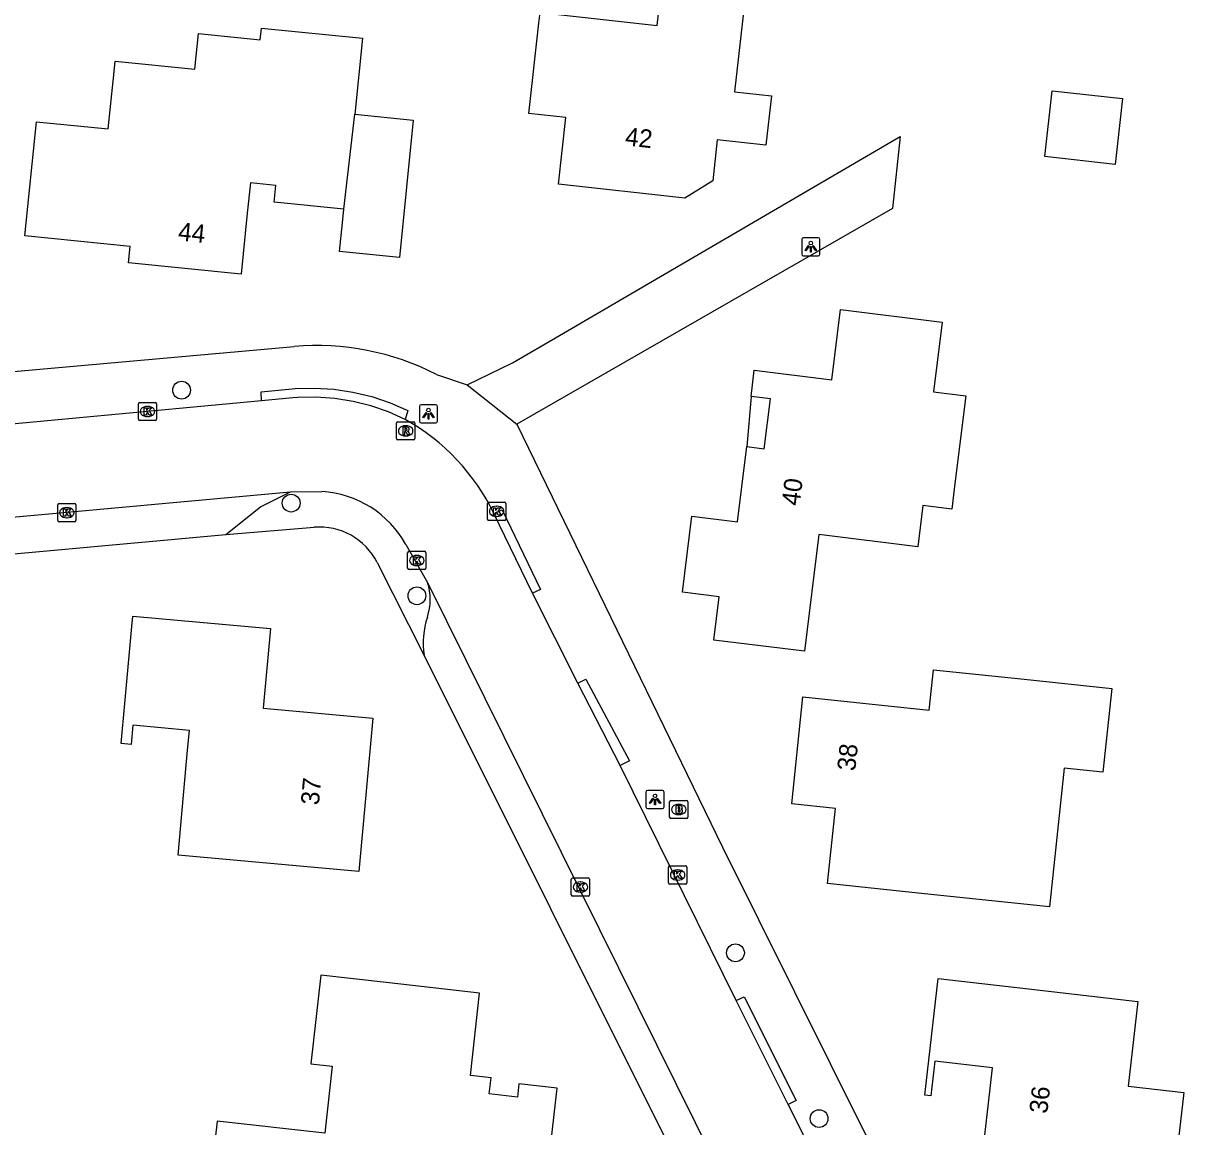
# Model space of a CAD drawing. Extents: x 162398 to 163643, y 386453 to 387397.
# Drawn here: x 163120.8 to 163184.6, y 386684.2 to 386744.8 of the extents above; entities that cross this region are included whole.
import ezdxf

# ---------------------------------------------------------------- set-up
doc = ezdxf.new("R2010")
doc.units = 0
for name, color, linetype in [('IMGEO_Boom', 7, 'Continuous'), ('IMGEO_Brandkraan', 7, 'Continuous'), ('IMGEO_Kolk', 7, 'Continuous'), ('IMGEO_Lichtpunt', 7, 'Continuous'), ('IMGEO_Pand', 7, 'Continuous'), ('IMGEO_Pand_nummerreeks', 7, 'Continuous'), ('IMGEO_Pand_overbouw', 7, 'Continuous'), ('IMGEO_Parkeervlak_open', 7, 'Continuous'), ('IMGEO_Rijbaan_lokaal_open', 7, 'Continuous'), ('IMGEO_Rioolput', 7, 'Continuous'), ('IMGEO_Voetpad_open', 7, 'Continuous')]:
    doc.layers.add(name, color=color, linetype=linetype)

msp = doc.modelspace()

# ---------------------------------------------------------------- linework, layer by layer
at = {"layer": 'IMGEO_Boom'}
for centre in [(163129.517, 386724.678), (163135.538, 386718.476), (163142.45, 386713.386), (163159.955, 386693.777), (163164.55, 386684.674)]:
    msp.add_circle(centre, 0.489, dxfattribs=at)
at = {"layer": 'IMGEO_Brandkraan'}
for p, q in [((163156.337, 386701.223), (163156.337, 386702.075)), ((163156.412, 386702.149), (163157.264, 386702.149)), ((163156.825, 386701.929), (163156.85, 386701.929)), ((163157.338, 386702.075), (163157.338, 386701.223)), ((163156.848, 386701.369), (163156.823, 386701.369)), ((163157.264, 386701.149), (163156.412, 386701.149))]:
    msp.add_line(p, q, dxfattribs=at)
for points in [[(163156.337, 386701.223), (163156.337, 386702.075)], [(163156.412, 386702.149), (163157.264, 386702.149)], [(163156.685, 386701.849), (163156.685, 386701.449), (163156.898, 386701.449)], [(163156.916, 386701.849), (163156.685, 386701.849)], [(163157.338, 386702.075), (163157.338, 386701.223)], [(163156.864, 386701.768), (163156.81, 386701.768), (163156.81, 386701.692)], [(163156.81, 386701.692), (163156.863, 386701.692)], [(163156.872, 386701.616), (163156.81, 386701.616), (163156.81, 386701.535)], [(163156.81, 386701.535), (163156.872, 386701.535)], [(163157.264, 386701.149), (163156.412, 386701.149)]]:
    msp.add_lwpolyline(points, dxfattribs=at)
for centre, radius, start, end in [((163156.414, 386702.073), 0.0765, 91.55205, 178.44795), ((163156.414, 386702.073), 0.0765, 91.55205, 178.44795), ((163156.92, 386701.704), 0.145, 59.4692, 91.53667), ((163156.945, 386701.751), 0.0922, 285.51372, 58.15012), ((163157.262, 386702.073), 0.0765, 1.55205, 88.44795), ((163157.262, 386702.073), 0.0765, 1.55205, 88.44795), ((163156.414, 386701.225), 0.0765, 181.55205, 268.44795), ((163156.414, 386701.225), 0.0765, 181.55205, 268.44795), ((163156.865, 386701.73), 0.0379, 267.82845, 90.93552), ((163156.873, 386701.575), 0.0404, 269.87594, 90.50774), ((163156.904, 386701.7), 0.251, 268.66757, 293.53466), ((163156.95, 386701.559), 0.105, 301.31148, 78.98903), ((163157.262, 386701.225), 0.0765, 271.55205, 358.44795), ((163157.262, 386701.225), 0.0765, 271.55205, 358.44795)]:
    msp.add_arc(centre, radius, start, end, dxfattribs=at)
for centre, major_axis, ratio, start_param, end_param in [((163156.824, 386701.649), (-0.387, 0.002), 0.722429, 4.712389, 7.853982), ((163156.849, 386701.649), (-0.39, 0.002), 0.717154, 1.570796, 4.712389)]:
    msp.add_ellipse(centre, major_axis=major_axis, ratio=ratio, start_param=start_param, end_param=end_param, dxfattribs=at)
at = {"layer": 'IMGEO_Kolk'}
for p, q in [((163127.141, 386723.082), (163127.141, 386723.934)), ((163127.216, 386724.008), (163128.068, 386724.008)), ((163127.629, 386723.788), (163127.654, 386723.788)), ((163128.142, 386723.934), (163128.142, 386723.082)), ((163128.068, 386723.008), (163127.216, 386723.008)), ((163127.652, 386723.228), (163127.627, 386723.228)), ((163122.783, 386718.453), (163123.635, 386718.453)), ((163146.33, 386717.596), (163146.33, 386718.448)), ((163146.405, 386718.522), (163147.257, 386718.522)), ((163147.331, 386718.448), (163147.331, 386717.596)), ((163122.708, 386717.527), (163122.708, 386718.379)), ((163123.196, 386718.233), (163123.221, 386718.233)), ((163123.709, 386718.379), (163123.709, 386717.527)), ((163146.818, 386718.302), (163146.843, 386718.302)), ((163123.635, 386717.453), (163122.783, 386717.453)), ((163123.219, 386717.673), (163123.194, 386717.673)), ((163147.257, 386717.522), (163146.405, 386717.522)), ((163146.841, 386717.742), (163146.816, 386717.742)), ((163141.939, 386714.902), (163141.939, 386715.754)), ((163142.014, 386715.828), (163142.866, 386715.828)), ((163142.427, 386715.608), (163142.452, 386715.608)), ((163142.94, 386715.754), (163142.94, 386714.902)), ((163142.866, 386714.828), (163142.014, 386714.828)), ((163142.45, 386715.048), (163142.425, 386715.048)), ((163156.278, 386697.627), (163156.278, 386698.479)), ((163156.353, 386698.553), (163157.205, 386698.553)), ((163156.766, 386698.333), (163156.791, 386698.333)), ((163157.279, 386698.479), (163157.279, 386697.627)), ((163150.933, 386696.962), (163150.933, 386697.814)), ((163151.008, 386697.888), (163151.86, 386697.888)), ((163151.421, 386697.668), (163151.446, 386697.668)), ((163151.934, 386697.814), (163151.934, 386696.962)), ((163157.205, 386697.553), (163156.353, 386697.553)), ((163156.789, 386697.773), (163156.764, 386697.773)), ((163151.86, 386696.888), (163151.008, 386696.888)), ((163151.444, 386697.108), (163151.419, 386697.108))]:
    msp.add_line(p, q, dxfattribs=at)
for points in [[(163127.141, 386723.082), (163127.141, 386723.934)], [(163127.216, 386724.008), (163128.068, 386724.008)], [(163127.462, 386723.708), (163127.585, 386723.708), (163127.585, 386723.557), (163127.715, 386723.708), (163127.879, 386723.708), (163127.733, 386723.557), (163127.886, 386723.308), (163127.734, 386723.308), (163127.649, 386723.472), (163127.585, 386723.405), (163127.585, 386723.308), (163127.462, 386723.308), (163127.462, 386723.708)], [(163128.142, 386723.934), (163128.142, 386723.082)], [(163128.068, 386723.008), (163127.216, 386723.008)], [(163122.783, 386718.453), (163123.635, 386718.453)], [(163146.33, 386717.596), (163146.33, 386718.448)], [(163146.405, 386718.522), (163147.257, 386718.522)], [(163147.331, 386718.448), (163147.331, 386717.596)], [(163122.708, 386717.527), (163122.708, 386718.379)], [(163123.029, 386718.153), (163123.152, 386718.153), (163123.152, 386718.002), (163123.282, 386718.153), (163123.446, 386718.153), (163123.3, 386718.002), (163123.453, 386717.753), (163123.301, 386717.753), (163123.216, 386717.917), (163123.152, 386717.85), (163123.152, 386717.753), (163123.029, 386717.753), (163123.029, 386718.153)], [(163123.709, 386718.379), (163123.709, 386717.527)], [(163146.651, 386718.222), (163146.774, 386718.222), (163146.774, 386718.071), (163146.904, 386718.222), (163147.068, 386718.222), (163146.922, 386718.071), (163147.075, 386717.822), (163146.923, 386717.822), (163146.838, 386717.986), (163146.774, 386717.919), (163146.774, 386717.822), (163146.651, 386717.822), (163146.651, 386718.222)], [(163123.635, 386717.453), (163122.783, 386717.453)], [(163147.257, 386717.522), (163146.405, 386717.522)], [(163141.939, 386714.902), (163141.939, 386715.754)], [(163142.014, 386715.828), (163142.866, 386715.828)], [(163142.26, 386715.528), (163142.383, 386715.528), (163142.383, 386715.377), (163142.513, 386715.528), (163142.677, 386715.528), (163142.531, 386715.377), (163142.684, 386715.128), (163142.532, 386715.128), (163142.447, 386715.292), (163142.383, 386715.225), (163142.383, 386715.128), (163142.26, 386715.128), (163142.26, 386715.528)], [(163142.94, 386715.754), (163142.94, 386714.902)], [(163142.866, 386714.828), (163142.014, 386714.828)], [(163156.278, 386697.627), (163156.278, 386698.479)], [(163156.353, 386698.553), (163157.205, 386698.553)], [(163156.599, 386698.253), (163156.722, 386698.253), (163156.722, 386698.102), (163156.852, 386698.253), (163157.016, 386698.253), (163156.87, 386698.102), (163157.023, 386697.853), (163156.871, 386697.853), (163156.786, 386698.017), (163156.722, 386697.95), (163156.722, 386697.853), (163156.599, 386697.853), (163156.599, 386698.253)], [(163157.279, 386698.479), (163157.279, 386697.627)], [(163150.933, 386696.962), (163150.933, 386697.814)], [(163151.008, 386697.888), (163151.86, 386697.888)], [(163151.254, 386697.588), (163151.377, 386697.588), (163151.377, 386697.437), (163151.507, 386697.588), (163151.671, 386697.588), (163151.525, 386697.437), (163151.678, 386697.188), (163151.526, 386697.188), (163151.441, 386697.352), (163151.377, 386697.285), (163151.377, 386697.188), (163151.254, 386697.188), (163151.254, 386697.588)], [(163151.934, 386697.814), (163151.934, 386696.962)], [(163157.205, 386697.553), (163156.353, 386697.553)], [(163151.86, 386696.888), (163151.008, 386696.888)]]:
    msp.add_lwpolyline(points, dxfattribs=at)
for centre, start, end in [((163127.218, 386723.932), 91.55205, 178.44795), ((163127.218, 386723.932), 91.55205, 178.44795), ((163128.066, 386723.932), 1.55205, 88.44795), ((163128.066, 386723.932), 1.55205, 88.44795), ((163127.218, 386723.084), 181.55205, 268.44795), ((163127.218, 386723.084), 181.55205, 268.44795), ((163128.066, 386723.084), 271.55205, 358.44795), ((163128.066, 386723.084), 271.55205, 358.44795), ((163122.785, 386718.377), 91.55205, 178.44795), ((163122.785, 386718.377), 91.55205, 178.44795), ((163123.633, 386718.377), 1.55205, 88.44795), ((163123.633, 386718.377), 1.55205, 88.44795), ((163146.407, 386718.446), 91.55205, 178.44795), ((163146.407, 386718.446), 91.55205, 178.44795), ((163147.255, 386718.446), 1.55205, 88.44795), ((163147.255, 386718.446), 1.55205, 88.44795), ((163122.785, 386717.529), 181.55205, 268.44795), ((163122.785, 386717.529), 181.55205, 268.44795), ((163123.633, 386717.529), 271.55205, 358.44795), ((163123.633, 386717.529), 271.55205, 358.44795), ((163146.407, 386717.598), 181.55205, 268.44795), ((163146.407, 386717.598), 181.55205, 268.44795), ((163147.255, 386717.598), 271.55205, 358.44795), ((163147.255, 386717.598), 271.55205, 358.44795), ((163142.016, 386715.752), 91.55205, 178.44795), ((163142.016, 386715.752), 91.55205, 178.44795), ((163142.864, 386715.752), 1.55205, 88.44795), ((163142.864, 386715.752), 1.55205, 88.44795), ((163142.016, 386714.904), 181.55205, 268.44795), ((163142.016, 386714.904), 181.55205, 268.44795), ((163142.864, 386714.904), 271.55205, 358.44795), ((163142.864, 386714.904), 271.55205, 358.44795), ((163156.355, 386698.477), 91.55205, 178.44795), ((163156.355, 386698.477), 91.55205, 178.44795), ((163157.203, 386698.477), 1.55205, 88.44795), ((163157.203, 386698.477), 1.55205, 88.44795), ((163151.01, 386697.812), 91.55205, 178.44795), ((163151.01, 386697.812), 91.55205, 178.44795), ((163151.858, 386697.812), 1.55205, 88.44795), ((163151.858, 386697.812), 1.55205, 88.44795), ((163156.355, 386697.629), 181.55205, 268.44795), ((163156.355, 386697.629), 181.55205, 268.44795), ((163157.203, 386697.629), 271.55205, 358.44795), ((163157.203, 386697.629), 271.55205, 358.44795), ((163151.01, 386696.964), 181.55205, 268.44795), ((163151.01, 386696.964), 181.55205, 268.44795), ((163151.858, 386696.964), 271.55205, 358.44795), ((163151.858, 386696.964), 271.55205, 358.44795)]:
    msp.add_arc(centre, 0.0765, start, end, dxfattribs=at)
for centre, major_axis, ratio, start_param, end_param in [((163127.628, 386723.508), (-0.387, 0.002), 0.722429, 4.712389, 7.853982), ((163127.653, 386723.508), (-0.39, 0.002), 0.717154, 1.570796, 4.712389), ((163123.195, 386717.953), (-0.387, 0.002), 0.722429, 4.712389, 7.853982), ((163123.22, 386717.953), (-0.39, 0.002), 0.717154, 1.570796, 4.712389), ((163146.817, 386718.022), (-0.387, 0.002), 0.722429, 4.712389, 7.853982), ((163146.842, 386718.022), (-0.39, 0.002), 0.717154, 1.570796, 4.712389), ((163142.426, 386715.328), (-0.387, 0.002), 0.722429, 4.712389, 7.853982), ((163142.451, 386715.328), (-0.39, 0.002), 0.717154, 1.570796, 4.712389), ((163156.765, 386698.053), (-0.387, 0.002), 0.722429, 4.712389, 7.853982), ((163156.79, 386698.053), (-0.39, 0.002), 0.717154, 1.570796, 4.712389), ((163151.42, 386697.388), (-0.387, 0.002), 0.722429, 4.712389, 7.853982), ((163151.445, 386697.388), (-0.39, 0.002), 0.717154, 1.570796, 4.712389)]:
    msp.add_ellipse(centre, major_axis=major_axis, ratio=ratio, start_param=start_param, end_param=end_param, dxfattribs=at)
at = {"layer": 'IMGEO_Lichtpunt'}
for p, q in [((163163.598, 386732.957), (163163.598, 386732.15)), ((163163.598, 386732.957), (163163.598, 386732.15)), ((163164.5, 386733.052), (163163.692, 386733.052)), ((163164.5, 386733.052), (163163.692, 386733.052)), ((163164.594, 386732.15), (163164.594, 386732.957)), ((163164.594, 386732.15), (163164.594, 386732.957)), ((163163.692, 386732.056), (163164.5, 386732.056)), ((163163.692, 386732.056), (163164.5, 386732.056)), ((163142.583, 386723.785), (163142.583, 386722.978)), ((163142.583, 386723.785), (163142.583, 386722.978)), ((163143.485, 386723.88), (163142.677, 386723.88)), ((163143.485, 386723.88), (163142.677, 386723.88)), ((163143.579, 386722.978), (163143.579, 386723.785)), ((163143.579, 386722.978), (163143.579, 386723.785)), ((163142.677, 386722.884), (163143.485, 386722.884)), ((163142.677, 386722.884), (163143.485, 386722.884)), ((163155.035, 386702.602), (163155.035, 386701.795)), ((163155.035, 386702.602), (163155.035, 386701.795)), ((163155.937, 386702.697), (163155.129, 386702.697)), ((163155.937, 386702.697), (163155.129, 386702.697)), ((163156.031, 386701.795), (163156.031, 386702.602)), ((163156.031, 386701.795), (163156.031, 386702.602)), ((163155.129, 386701.701), (163155.937, 386701.701)), ((163155.129, 386701.701), (163155.937, 386701.701))]:
    msp.add_line(p, q, dxfattribs=at)
for points in [[(163163.972, 386732.621), (163164.011, 386732.593), (163163.823, 386732.331), (163163.785, 386732.358), (163163.972, 386732.621)], [(163164.074, 386732.573), (163164.121, 386732.573), (163164.121, 386732.251), (163164.074, 386732.251), (163164.074, 386732.573)], [(163164.184, 386732.593), (163164.222, 386732.62), (163164.409, 386732.358), (163164.37, 386732.33), (163164.184, 386732.593)], [(163142.957, 386723.449), (163142.996, 386723.421), (163142.808, 386723.159), (163142.77, 386723.186), (163142.957, 386723.449)], [(163143.059, 386723.401), (163143.106, 386723.401), (163143.106, 386723.079), (163143.059, 386723.079), (163143.059, 386723.401)], [(163143.169, 386723.421), (163143.207, 386723.448), (163143.394, 386723.186), (163143.355, 386723.158), (163143.169, 386723.421)], [(163155.409, 386702.266), (163155.448, 386702.238), (163155.26, 386701.976), (163155.222, 386702.003), (163155.409, 386702.266)], [(163155.511, 386702.218), (163155.558, 386702.218), (163155.558, 386701.896), (163155.511, 386701.896), (163155.511, 386702.218)], [(163155.621, 386702.238), (163155.659, 386702.265), (163155.846, 386702.003), (163155.807, 386701.975), (163155.621, 386702.238)]]:
    msp.add_lwpolyline(points, dxfattribs=at)
for centre in [(163164.097, 386732.755), (163143.082, 386723.583), (163155.534, 386702.4)]:
    msp.add_circle(centre, 0.0994, dxfattribs=at)
for centre, start, end in [((163163.692, 386732.957), 90, 180), ((163163.692, 386732.957), 90, 180), ((163164.5, 386732.957), 0, 90), ((163164.5, 386732.957), 0, 90), ((163163.692, 386732.15), 180, 270), ((163163.692, 386732.15), 180, 270), ((163164.5, 386732.15), 270, 0), ((163164.5, 386732.15), 270, 360), ((163142.677, 386723.785), 90, 180), ((163142.677, 386723.785), 90, 180), ((163143.485, 386723.785), 0, 90), ((163143.485, 386723.785), 0, 90), ((163142.677, 386722.978), 180, 270), ((163142.677, 386722.978), 180, 270), ((163143.485, 386722.978), 270, 0), ((163143.485, 386722.978), 270, 360), ((163155.129, 386702.602), 90, 180), ((163155.129, 386702.602), 90, 180), ((163155.937, 386702.602), 0, 90), ((163155.937, 386702.602), 0, 90), ((163155.129, 386701.795), 180, 270), ((163155.129, 386701.795), 180, 270), ((163155.937, 386701.795), 270, 0), ((163155.937, 386701.795), 270, 360)]:
    msp.add_arc(centre, 0.0946, start, end, dxfattribs=at)
at = {"layer": 'IMGEO_Pand'}
for points in [[(163150.221, 386736.002), (163150.626, 386739.649), (163148.597, 386739.874), (163149.149, 386744.844), (163149.213, 386745.417), (163155.657, 386744.701), (163156.067, 386748.394), (163160.664, 386747.883), (163159.907, 386741.069), (163161.93, 386740.844), (163161.629, 386738.133), (163158.956, 386738.43), (163158.706, 386736.18), (163157.165, 386735.23), (163150.221, 386736.002)], [(163138.433, 386734.62), (163134.601, 386735.006), (163134.693, 386735.922), (163133.294, 386736.063), (163133.126, 386734.394), (163132.789, 386731.051), (163126.6, 386731.675), (163126.69, 386732.57), (163120.909, 386733.152), (163121.54, 386739.421), (163125.484, 386739.024), (163125.783, 386741.991), (163125.86, 386742.753), (163130.25, 386742.311), (163130.447, 386744.262), (163133.836, 386743.92), (163133.901, 386744.565), (163139.455, 386744.006), (163139.035, 386739.832)], [(163176.957, 386737.513), (163177.363, 386741.125), (163181.23, 386740.69), (163180.824, 386737.078), (163176.957, 386737.513)], [(163139.035, 386739.832), (163142.244, 386739.509), (163141.484, 386731.961), (163138.198, 386732.292), (163138.357, 386733.867), (163138.433, 386734.62)], [(163138.433, 386734.62), (163139.035, 386739.832)], [(163164.546, 386716.746), (163163.757, 386710.339), (163158.768, 386710.954), (163159.061, 386713.334), (163157.046, 386713.583), (163157.561, 386717.761), (163160.068, 386717.452), (163160.577, 386721.584), (163161.536, 386721.466), (163161.874, 386724.208), (163160.81, 386724.339), (163160.987, 386725.772), (163165.248, 386725.247), (163165.724, 386729.103), (163171.318, 386728.413), (163170.846, 386724.587), (163172.614, 386724.369), (163172.002, 386719.407), (163171.847, 386718.151), (163170.254, 386718.347), (163169.974, 386716.077), (163164.546, 386716.746)], [(163129.325, 386699.138), (163129.845, 386704.912), (163129.942, 386705.993), (163126.845, 386706.272), (163126.751, 386705.223), (163126.202, 386705.272), (163126.4, 386707.47), (163126.782, 386711.703), (163126.833, 386712.27), (163134.393, 386711.589), (163134, 386707.217), (163140.024, 386706.674), (163139.264, 386698.243), (163129.325, 386699.138)], [(163169.992, 386697.06), (163165.019, 386697.582), (163165.452, 386701.7), (163163.049, 386701.952), (163163.666, 386707.834), (163170.608, 386707.105), (163170.841, 386709.324), (163175.814, 386708.802), (163180.631, 386708.296), (163180.148, 386703.698), (163178.019, 386703.921), (163177.219, 386696.302), (163169.992, 386697.06)], [(163146.421, 386686.029), (163146.521, 386686.908), (163145.387, 386687.036), (163145.897, 386691.563), (163140.929, 386692.124), (163137.171, 386692.548), (163136.622, 386687.682), (163137.795, 386687.55), (163137.381, 386683.873), (163131.471, 386684.538), (163130.905, 386679.525), (163138.51, 386678.666), (163138.658, 386679.979), (163144.328, 386679.34), (163149.296, 386678.779), (163150.149, 386686.343), (163148.058, 386686.579), (163147.976, 386685.854), (163146.421, 386686.029)], [(163181.54, 386686.451), (163184.594, 386686.103), (163183.742, 386678.629), (163183.343, 386678.674), (163183.401, 386679.175), (163177.536, 386679.843), (163177.444, 386679.039), (163176.436, 386679.154), (163176.519, 386679.882), (163173.255, 386680.254), (163173.855, 386685.523), (163174.076, 386687.46), (163170.913, 386687.82), (163170.696, 386685.914), (163170.357, 386685.952), (163171.087, 386692.36), (163176.055, 386691.794), (163182.07, 386691.109), (163181.54, 386686.451)]]:
    msp.add_lwpolyline(points, dxfattribs=at)
at = {"layer": 'IMGEO_Pand_overbouw'}
msp.add_lwpolyline([(163161.874, 386724.208), (163160.81, 386724.339), (163160.577, 386721.584), (163161.536, 386721.466)], close=True, dxfattribs=at)
at = {"layer": 'IMGEO_Parkeervlak_open'}
for points in [[(163106.635, 386714.454), (163131.948, 386716.758)], [(163142.845, 386710.112), (163170.644, 386654.483)]]:
    msp.add_lwpolyline(points, dxfattribs=at)
at = {"layer": 'IMGEO_Rijbaan_lokaal_open'}
for points in [[(163141.811, 386723.064), (163140.884, 386723.484), (163139.923, 386723.819), (163138.936, 386724.066), (163137.931, 386724.225), (163136.916, 386724.293), (163135.898, 386724.271), (163135.635, 386724.25), (163133.912, 386724.09)], [(163133.912, 386724.09), (163118.21, 386722.627)], [(163103.144, 386716.11), (163103.286, 386716.164), (163135.507, 386719.088)], [(163135.507, 386719.088), (163137.228, 386719.108)], [(163148.797, 386713.522), (163146.679, 386717.903)], [(163141.845, 386716.199), (163143.039, 386714.124)], [(163143.039, 386714.124), (163158.79, 386682.361), (163170.35, 386659.122)], [(163151.289, 386708.591), (163148.797, 386713.522)], [(163153.617, 386704.068), (163151.289, 386708.591)], [(163160.001, 386691.151), (163153.617, 386704.068)], [(163162.859, 386685.444), (163160.001, 386691.151)], [(163168.446, 386674.337), (163162.859, 386685.444)]]:
    msp.add_lwpolyline(points, dxfattribs=at)
for centre, radius, start, end in [((163136.112, 386712.812), 11.729, 25.72248, 60.93065), ((163136.889, 386713.452), 5.666, 28.99989, 86.57311)]:
    msp.add_arc(centre, radius, start, end, dxfattribs=at)
at = {"layer": 'IMGEO_Rioolput'}
for p, q in [((163141.331, 386722.02), (163141.331, 386722.872)), ((163141.406, 386722.946), (163142.258, 386722.946)), ((163142.332, 386722.872), (163142.332, 386722.02)), ((163141.819, 386722.726), (163141.844, 386722.726)), ((163142.258, 386721.946), (163141.406, 386721.946)), ((163141.842, 386722.166), (163141.817, 386722.166))]:
    msp.add_line(p, q, dxfattribs=at)
for points in [[(163141.331, 386722.02), (163141.331, 386722.872)], [(163141.406, 386722.946), (163142.258, 386722.946)], [(163142.332, 386722.872), (163142.332, 386722.02)], [(163141.92, 386722.644), (163141.668, 386722.646), (163141.668, 386722.246)], [(163141.668, 386722.246), (163141.792, 386722.246), (163141.792, 386722.408), (163141.803, 386722.408)], [(163141.846, 386722.565), (163141.792, 386722.565), (163141.792, 386722.484)], [(163141.792, 386722.484), (163141.844, 386722.484)], [(163141.85, 386722.379), (163141.921, 386722.246), (163142.061, 386722.246), (163141.996, 386722.372)], [(163142.258, 386721.946), (163141.406, 386721.946)]]:
    msp.add_lwpolyline(points, dxfattribs=at)
for centre, radius, start, end in [((163141.408, 386722.87), 0.0765, 91.55205, 178.44795), ((163141.408, 386722.87), 0.0765, 91.55205, 178.44795), ((163142.256, 386722.87), 0.0765, 1.55205, 88.44795), ((163142.256, 386722.87), 0.0765, 1.55205, 88.44795), ((163141.802, 386722.355), 0.0533, 26.02933, 88.69889), ((163141.828, 386722.673), 0.19, 274.7715, 282.96867), ((163141.852, 386722.469), 0.0964, 77.00612, 93.18647), ((163141.866, 386722.526), 0.0378, 276.66336, 79.67722), ((163141.919, 386722.534), 0.109, 350.36119, 89.41601), ((163141.917, 386722.534), 0.112, 277.58423, 350.98172), ((163141.901, 386722.319), 0.108, 29.51342, 73.79051), ((163141.408, 386722.022), 0.0765, 181.55205, 268.44795), ((163141.408, 386722.022), 0.0765, 181.55205, 268.44795), ((163142.256, 386722.022), 0.0765, 271.55205, 358.44795), ((163142.256, 386722.022), 0.0765, 271.55205, 358.44795)]:
    msp.add_arc(centre, radius, start, end, dxfattribs=at)
for centre, major_axis, ratio, start_param, end_param in [((163141.818, 386722.446), (-0.387, 0.002), 0.722429, 4.712389, 7.853982), ((163141.843, 386722.446), (-0.39, 0.002), 0.717154, 1.570796, 4.712389)]:
    msp.add_ellipse(centre, major_axis=major_axis, ratio=ratio, start_param=start_param, end_param=end_param, dxfattribs=at)
at = {"layer": 'IMGEO_Voetpad_open'}
for points in [[(163145.202, 386724.977), (163147.694, 386726.173), (163150.289, 386727.687), (163169.003, 386738.606), (163168.577, 386734.666), (163147.937, 386722.815)], [(163089.245, 386722.934), (163135.707, 386727.073)], [(163143.518, 386725.545), (163145.202, 386724.977)], [(163133.912, 386724.09), (163133.881, 386724.589), (163135.59, 386724.748), (163135.762, 386724.762), (163136.823, 386724.795), (163137.884, 386724.733), (163138.934, 386724.577), (163139.967, 386724.327), (163140.973, 386723.986), (163141.944, 386723.557), (163141.811, 386723.064)], [(163145.202, 386724.977), (163147.937, 386722.815)], [(163147.937, 386722.815), (163159.239, 386699.578), (163180.984, 386655.913)], [(163131.948, 386716.758), (163133.859, 386718.264), (163135.507, 386719.088)], [(163146.679, 386717.903), (163147.131, 386718.115), (163149.249, 386713.734), (163148.797, 386713.522)], [(163131.948, 386716.758), (163136.803, 386717.15)], [(163140.267, 386715.208), (163142.845, 386710.112)], [(163151.289, 386708.591), (163151.737, 386708.811), (163154.131, 386704.321), (163153.617, 386704.068)], [(163160.001, 386691.151), (163160.44, 386691.367), (163163.292, 386685.658), (163162.859, 386685.444)]]:
    msp.add_lwpolyline(points, dxfattribs=at)
for centre, radius, start, end in [((163136.954, 386712.717), 14.41, 62.89982, 94.96315), ((163137.094, 386713.609), 3.553, 26.74468, 94.70329), ((163140.115, 386713.198), 3.067, 341.40451, 17.57238), ((163147.334, 386710.796), 4.541, 161.73114, 188.6696)]:
    msp.add_arc(centre, radius, start, end, dxfattribs=at)

# ---------------------------------------------------------------- texts
at = {"layer": 'IMGEO_Pand_nummerreeks'}
for s, rotation, p in [('42', 353.65618, (163153.856, 386738.132)), ('44', 354.24177, (163129.291, 386732.911)), ('40', 82.9774, (163163.478, 386718.299)), ('38', 84.01178, (163166.534, 386703.731)), ('37', 84.84908, (163137.06, 386701.862)), ('36', 83.50016, (163177.087, 386684.915))]:
    msp.add_text(s, height=1, rotation=rotation, dxfattribs=at).set_placement(p)

doc.saveas('drawing.dxf')
